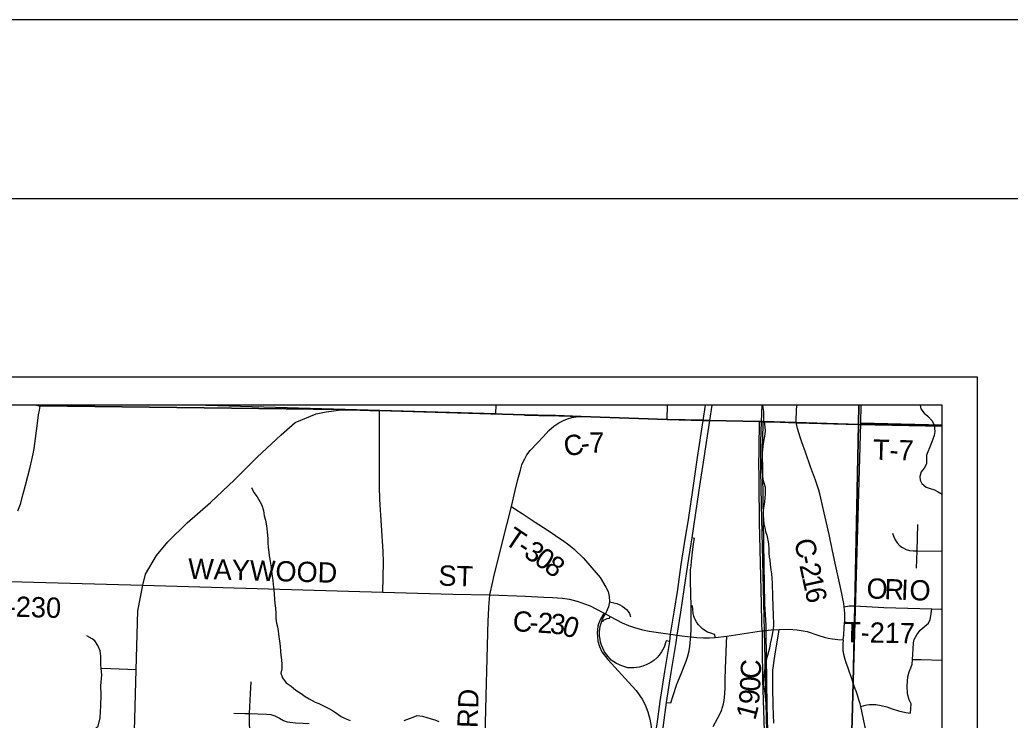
# Model space of a CAD drawing. Extents: x 0 to 34, y 0 to 22.
# Drawn here: x 7.053 to 9.827, y 20.038 to 22 of the extents above; entities that cross this region are included whole.
import ezdxf

# ---------------------------------------------------------------- set-up
doc = ezdxf.new("R2010")
doc.units = 0
for name, color, linetype in [('GM_X_Corporation', 7, 'Continuous'), ('GM_X_County_Road', 7, 'Continuous'), ('GM_X_County_Road_Text', 7, 'Continuous'), ('GM_X_Interchange_Ramps', 7, 'Continuous'), ('GM_X_Interstate_Route', 7, 'Continuous'), ('GM_X_Minor_River', 7, 'Continuous'), ('GM_X_Rail_Line', 7, 'Continuous'), ('GM_X_State_Route', 7, 'Continuous'), ('GM_X_Township_Road', 7, 'Continuous'), ('GM_X_Township_Road_Text', 7, 'Continuous'), ('SH_Border', 7, 'Continuous'), ('SH_Cut_Line', 7, 'Continuous'), ('SH_Data', 7, 'Continuous')]:
    doc.layers.add(name, color=color, linetype=linetype)

msp = doc.modelspace()

# ---------------------------------------------------------------- linework, layer by layer
at = {"layer": 'GM_X_Corporation'}
for points in [[(7.1023, 20.9204), (2.837, 20.9204), (2.837, 14.1204), (9.637, 14.1204), (9.637, 20.9204), (9.4036, 20.9204), (9.4022, 20.8667), (9.2273, 20.8723), (9.1354, 20.8749), (9.124, 20.8753), (8.9858, 20.878), (8.9676, 20.8785), (8.8663, 20.881), (8.6259, 20.8892), (8.5535, 20.8914), (8.5421, 20.8915), (8.4667, 20.8934), (8.0602, 20.9055), (7.9522, 20.9084), (7.1104, 20.9188)], [(9.4036, 20.9204), (7.1023, 20.9204), (7.1104, 20.9188), (7.9522, 20.9084), (8.0602, 20.9055), (8.4667, 20.8934), (8.5421, 20.8915), (8.5535, 20.8914), (8.6259, 20.8892), (8.8663, 20.881), (8.9676, 20.8785), (8.9858, 20.878), (9.124, 20.8753), (9.1354, 20.8749), (9.2273, 20.8723), (9.4022, 20.8667)], [(9.4038, 20.9204), (7.1023, 20.9204), (7.1104, 20.9188), (7.9522, 20.9084), (8.0602, 20.9055), (8.4667, 20.8934), (8.5422, 20.8918), (8.5472, 20.8916), (8.563, 20.8911), (8.6259, 20.8892), (8.8663, 20.881), (8.9858, 20.878), (9.124, 20.8753), (9.1354, 20.8749), (9.2299, 20.8713), (9.4022, 20.8667)], [(9.4036, 20.9204), (7.1023, 20.9204), (7.1104, 20.9188), (7.9522, 20.9084), (8.0602, 20.9055), (8.4667, 20.8934), (8.5421, 20.8915), (8.5535, 20.8914), (8.6259, 20.8892), (8.8663, 20.881), (8.9676, 20.8785), (8.9858, 20.878), (9.124, 20.8753), (9.1354, 20.8749), (9.2273, 20.8723), (9.4022, 20.8667)], [(8.3873, 20.9204), (7.5744, 20.9204), (8.3863, 20.8974)], [(9.637, 20.8621), (9.637, 20.9204), (9.4036, 20.9204), (9.4022, 20.8667)], [(9.637, 20.8648), (9.637, 20.9204), (9.4094, 20.9204), (9.4079, 20.8705)], [(9.637, 19.791), (9.637, 20.8648), (9.4079, 20.8705), (9.3789, 19.8558), (9.3773, 19.7981)]]:
    msp.add_lwpolyline(points, close=True, dxfattribs=at)
for points in [[(9.3802, 19.8717), (9.3877, 20.1427), (9.3918, 20.3593), (9.4022, 20.8667), (9.2273, 20.8723), (9.1354, 20.8749), (9.124, 20.8753), (8.9858, 20.878), (8.9676, 20.8785), (8.8663, 20.881), (8.6259, 20.8892), (8.5535, 20.8914), (8.5421, 20.8915), (8.4667, 20.8934), (8.0602, 20.9055), (7.9522, 20.9084), (7.1104, 20.9188), (7.1023, 20.9204), (3.3169, 20.9204)], [(9.1487, 20.0085), (9.1468, 20.0776), (9.145, 20.218), (9.1441, 20.2844), (9.144, 20.2867), (9.144, 20.2897), (9.144, 20.2906), (9.1437, 20.3035), (9.1399, 20.3642), (9.1383, 20.4738), (9.1364, 20.5986), (9.1357, 20.6613), (9.1334, 20.7956), (9.1352, 20.8657), (9.1354, 20.8749), (9.124, 20.8753), (9.1238, 20.8716), (9.1239, 20.8698), (9.1226, 20.7411), (9.1229, 20.7362), (9.1234, 20.6964), (9.1243, 20.5991), (9.1244, 20.5932), (9.1298, 20.3645), (9.131, 20.3111), (9.1312, 20.3022), (9.1326, 20.2879), (9.1327, 20.2847), (9.133, 20.2451), (9.1337, 20.1498), (9.1348, 20.1234), (9.138, 20.0088)], [(9.637, 14.7553), (9.637, 20.8621), (9.4022, 20.8667), (9.3918, 20.3593), (9.3877, 20.1427), (9.3802, 19.8717)]]:
    msp.add_lwpolyline(points, dxfattribs=at)
at = {"layer": 'GM_X_County_Road'}
for p, q in [((7.0998, 20.9204), (7.1106, 20.9182)), ((8.8665, 20.8805), (8.8676, 20.9204)), ((7.9524, 20.9078), (8.0064, 20.9064)), ((8.0064, 20.9064), (8.0604, 20.905)), ((8.4669, 20.8929), (8.5469, 20.8907)), ((8.6261, 20.8886), (8.8665, 20.8805)), ((9.1376, 20.8743), (9.2275, 20.8718)), ((9.2275, 20.8718), (9.4024, 20.8662)), ((6.9433, 20.4291), (7.3976, 20.4163))]:
    msp.add_line(p, q, dxfattribs=at)
for points in [[(9.2275, 20.8718), (9.2293, 20.9101), (9.2306, 20.9204)], [(8.4633, 20.7616), (8.4676, 20.7708), (8.4738, 20.782), (8.4828, 20.7933), (8.5036, 20.8155), (8.5189, 20.832), (8.5354, 20.8502), (8.549, 20.8622), (8.5629, 20.8716)], [(8.5629, 20.8716), (8.5761, 20.8781), (8.5877, 20.8826), (8.5993, 20.8858), (8.6118, 20.8877), (8.6261, 20.8886)], [(8.8665, 20.8805), (8.9678, 20.878), (8.9769, 20.8777)], [(8.9769, 20.8777), (8.986, 20.8775), (9.1242, 20.8748), (9.1273, 20.8747)], [(9.1273, 20.8747), (9.1356, 20.8744), (9.1376, 20.8743)], [(9.3625, 20.3556), (9.3611, 20.3652), (9.3586, 20.3784), (9.3554, 20.3931), (9.3473, 20.4311), (9.3383, 20.4736), (9.3289, 20.5176), (9.3202, 20.5583), (9.3068, 20.6194), (9.2972, 20.6605), (9.2941, 20.6722), (9.2912, 20.6823), (9.2818, 20.7105), (9.2685, 20.7477), (9.2537, 20.7894), (9.2437, 20.8168), (9.239, 20.8307), (9.2313, 20.8557), (9.2275, 20.8718)], [(8.3812, 20.4403), (8.4041, 20.5339), (8.4301, 20.6367), (8.4409, 20.6821), (8.4486, 20.7123), (8.4554, 20.7387), (8.4595, 20.7534), (8.4633, 20.7616)], [(8.3659, 20.3308), (8.3666, 20.3556), (8.3695, 20.3894), (8.3778, 20.4265), (8.3812, 20.4403)], [(7.3976, 20.4163), (8.07, 20.3969), (8.2661, 20.3914), (8.3695, 20.3894)], [(8.3695, 20.3894), (8.4699, 20.3855), (8.5215, 20.3832), (8.5453, 20.3824), (8.5737, 20.3802), (8.5926, 20.377), (8.6134, 20.3717), (8.6144, 20.3714)], [(8.6144, 20.3714), (8.6354, 20.3645), (8.6511, 20.3584), (8.6669, 20.3506), (8.6899, 20.3386)], [(8.6899, 20.3386), (8.6938, 20.3364), (8.7071, 20.3289), (8.7242, 20.3194), (8.7403, 20.3114), (8.7585, 20.3035), (8.7748, 20.2979), (8.797, 20.2919), (8.8161, 20.288), (8.862, 20.2813)], [(9.3627, 20.2985), (9.3638, 20.3185), (9.364, 20.3383), (9.3637, 20.3466), (9.3625, 20.3556)], [(8.3538, 19.8762), (8.3599, 20.1063), (8.3625, 20.2113), (8.3655, 20.3184), (8.3659, 20.3308)], [(8.862, 20.2813), (8.8763, 20.2792), (8.8946, 20.2767), (8.9077, 20.2751), (8.9234, 20.2729), (8.9326, 20.2719), (8.9494, 20.2702), (8.9684, 20.2691), (8.9848, 20.2688), (9.0008, 20.2697), (9.0334, 20.2737), (9.1311, 20.2884)], [(9.1311, 20.2884), (9.1359, 20.2891), (9.141, 20.2896)], [(9.141, 20.2896), (9.1582, 20.2913), (9.1805, 20.2928)], [(9.1651, 20.03), (9.1638, 20.0783), (9.1624, 20.1314), (9.1621, 20.1505), (9.1623, 20.1665), (9.1629, 20.1787), (9.1641, 20.1914), (9.1662, 20.2056), (9.17, 20.2298), (9.1784, 20.2789), (9.1805, 20.2928)], [(9.1805, 20.2928), (9.2062, 20.2935), (9.2309, 20.2917), (9.2583, 20.2864), (9.2915, 20.2754), (9.3061, 20.2706), (9.3179, 20.268), (9.3301, 20.266), (9.3449, 20.2646), (9.36, 20.2633)], [(9.36, 20.2633), (9.3616, 20.2765), (9.3627, 20.2985)], [(9.3948, 20.1222), (9.3942, 20.1239), (9.3879, 20.1422), (9.3847, 20.1519), (9.3725, 20.1869), (9.3681, 20.1993), (9.365, 20.2088), (9.361, 20.2222), (9.3601, 20.2288), (9.3599, 20.2315), (9.3599, 20.2353), (9.3597, 20.2415), (9.3599, 20.2553), (9.3601, 20.2608), (9.36, 20.2633)], [(9.4223, 20.0149), (9.4203, 20.0231), (9.409, 20.0769), (9.4068, 20.0838), (9.4033, 20.0959), (9.3994, 20.1083), (9.3948, 20.1222)]]:
    msp.add_lwpolyline(points, dxfattribs=at)
at = {"layer": 'GM_X_Interchange_Ramps'}
msp.add_line((8.9334, 20.358), (8.9319, 20.4275), dxfattribs=at)
for points in [[(8.9319, 20.4275), (8.9317, 20.434), (8.9317, 20.452), (8.9319, 20.4591), (8.9334, 20.4712), (8.9346, 20.4835), (8.9379, 20.5094), (8.9407, 20.5323), (8.9427, 20.5471), (8.937, 20.5487)], [(8.6899, 20.3386), (8.6874, 20.3341), (8.6787, 20.3193), (8.6745, 20.3085), (8.6725, 20.3013), (8.6712, 20.2917), (8.6704, 20.283), (8.6712, 20.273), (8.6726, 20.2598), (8.6767, 20.2451), (8.6831, 20.2301), (8.7001, 20.2081), (8.7688, 20.1341), (8.7796, 20.1219), (8.7885, 20.1099), (8.7962, 20.0973), (8.805, 20.0811), (8.8125, 20.0622), (8.818, 20.0414), (8.8214, 20.0209), (8.8233, 19.9995), (8.8239, 19.9901), (8.832, 19.9897)], [(8.8736, 20.2591), (8.8635, 20.2606), (8.8579, 20.2431), (8.8503, 20.2299), (8.8444, 20.2209), (8.8375, 20.2132), (8.8296, 20.2059), (8.8208, 20.2002), (8.8095, 20.1945), (8.7981, 20.1898), (8.7877, 20.187), (8.7733, 20.1849), (8.7562, 20.1854), (8.7395, 20.1902), (8.7249, 20.1971), (8.7101, 20.2069), (8.6974, 20.2216), (8.6909, 20.2299), (8.686, 20.2398), (8.6826, 20.2482), (8.6802, 20.2569), (8.6785, 20.2653), (8.6773, 20.2748), (8.6769, 20.2846), (8.6781, 20.2951), (8.6797, 20.3045), (8.6826, 20.3132), (8.6842, 20.3178), (8.6858, 20.3224), (8.6913, 20.332), (8.6938, 20.3364)], [(8.9326, 20.2719), (8.9329, 20.2762), (8.9342, 20.2927), (8.9342, 20.3044), (8.9342, 20.3149), (8.934, 20.33), (8.934, 20.3372), (8.9334, 20.3489), (8.9334, 20.358)], [(9.0008, 20.2697), (9.0002, 20.2788), (8.9961, 20.2797), (8.9889, 20.2817), (8.9798, 20.2851), (8.9722, 20.2895), (8.9657, 20.2942), (8.96, 20.3001), (8.9535, 20.3068), (8.9487, 20.3138), (8.945, 20.32), (8.9431, 20.3242), (8.9414, 20.3297), (8.9396, 20.3374), (8.9386, 20.3481), (8.9374, 20.3583), (8.9334, 20.358)], [(8.6842, 20.3178), (8.6875, 20.3159), (8.6905, 20.3191), (8.6944, 20.3216), (8.6989, 20.323), (8.7047, 20.3243), (8.7071, 20.3289)], [(8.9121, 20.1847), (8.9194, 20.2037), (8.9239, 20.2149), (8.9286, 20.2329), (8.9303, 20.2444), (8.9319, 20.2651), (8.9326, 20.2719)], [(8.8651, 20.0879), (8.877, 20.0871), (8.8831, 20.1076), (8.8939, 20.1391), (8.9057, 20.1679), (8.9121, 20.1847)]]:
    msp.add_lwpolyline(points, dxfattribs=at)
at = {"layer": 'GM_X_Interstate_Route'}
for p, q in [((8.9678, 20.878), (8.9742, 20.9204)), ((8.986, 20.8775), (8.9925, 20.9204))]:
    msp.add_line(p, q, dxfattribs=at)
for points in [[(8.8273, 19.9603), (8.832, 19.9897), (8.8381, 20.0277), (8.8472, 20.0907), (8.8602, 20.1746), (8.8736, 20.2591), (8.8763, 20.2792), (8.8862, 20.3413), (8.8962, 20.4047), (8.9061, 20.4741), (8.9155, 20.533), (8.9181, 20.5506), (8.926, 20.5995), (8.9382, 20.6828), (8.9516, 20.774), (8.9678, 20.878)], [(8.8465, 19.9599), (8.8511, 19.9887), (8.8561, 20.0249), (8.8651, 20.0879), (8.8781, 20.1718), (8.8916, 20.2563), (8.8946, 20.2767), (8.9044, 20.3409), (8.9144, 20.4042), (8.9243, 20.4736), (8.9337, 20.5325), (8.937, 20.5487), (8.9564, 20.6824), (8.9699, 20.7735), (8.986, 20.8775)]]:
    msp.add_lwpolyline(points, dxfattribs=at)
at = {"layer": 'GM_X_Minor_River'}
for points in [[(9.1381, 20.8737), (9.1369, 20.8771), (9.1375, 20.8908), (9.137, 20.9033), (9.1353, 20.9139), (9.1345, 20.9204)], [(9.5751, 20.9204), (9.577, 20.9109), (9.5867, 20.8981), (9.597, 20.8899), (9.6089, 20.8768), (9.6147, 20.8643), (9.6165, 20.8472), (9.6147, 20.8362), (9.611, 20.8255), (9.6055, 20.811), (9.6015, 20.8015), (9.5963, 20.79), (9.5926, 20.7805), (9.5929, 20.7566), (9.5862, 20.7447), (9.5776, 20.734), (9.574, 20.7211), (9.5749, 20.7108), (9.5803, 20.701), (9.5918, 20.6909), (9.6036, 20.6876), (9.6158, 20.6832), (9.6257, 20.678), (9.637, 20.6719)], [(9.1381, 20.8737), (9.1401, 20.8603), (9.141, 20.8478), (9.1389, 20.8337), (9.1364, 20.8189), (9.1343, 20.8059), (9.1333, 20.796), (9.1326, 20.7865), (9.1324, 20.7763), (9.1321, 20.7653), (9.1319, 20.7554), (9.132, 20.7448), (9.1329, 20.7338), (9.1334, 20.7232), (9.1347, 20.7122), (9.1382, 20.7008), (9.141, 20.6906), (9.1412, 20.6716), (9.1406, 20.6617), (9.1388, 20.6492), (9.1374, 20.6389), (9.1357, 20.626), (9.1351, 20.6131), (9.136, 20.6017), (9.1377, 20.5884), (9.1401, 20.5774), (9.1421, 20.5668), (9.1453, 20.5566), (9.1485, 20.5422), (9.1505, 20.5324), (9.1514, 20.5176), (9.1516, 20.5058), (9.1524, 20.4963), (9.1537, 20.4865), (9.155, 20.4743), (9.1571, 20.4592), (9.1587, 20.4486), (9.16, 20.4357), (9.1605, 20.4243), (9.161, 20.414), (9.1613, 20.3928), (9.1618, 20.378), (9.1624, 20.3639), (9.1625, 20.3514), (9.1631, 20.3389), (9.1632, 20.3271), (9.1641, 20.3138), (9.1643, 20.3017), (9.1625, 20.2895), (9.1604, 20.2774), (9.1575, 20.264), (9.155, 20.2526), (9.1529, 20.2404), (9.15, 20.2298), (9.1478, 20.2199), (9.1449, 20.21), (9.142, 20.1963), (9.1399, 20.1845), (9.1385, 20.1731), (9.1375, 20.1636), (9.1362, 20.1484), (9.1363, 20.1377), (9.1388, 20.1203), (9.1412, 20.1059), (9.1421, 20.0957), (9.1434, 20.0839), (9.1439, 20.0725), (9.1448, 20.0581), (9.145, 20.046), (9.1455, 20.035)], [(7.7024, 20.6898), (7.709, 20.6762), (7.7183, 20.6638), (7.726, 20.6509), (7.7311, 20.6404), (7.7354, 20.6256), (7.7379, 20.6112), (7.7411, 20.5991), (7.7443, 20.5824), (7.7469, 20.5566), (7.7478, 20.5464), (7.7483, 20.535), (7.7492, 20.5217), (7.7505, 20.5089), (7.7521, 20.499), (7.7534, 20.4895), (7.7554, 20.477), (7.7571, 20.466), (7.7583, 20.4554), (7.7604, 20.4421), (7.7621, 20.4296), (7.763, 20.4183), (7.7643, 20.4038), (7.7656, 20.3913), (7.7665, 20.3773), (7.7674, 20.3652), (7.7691, 20.3526), (7.77, 20.3386), (7.7702, 20.3234), (7.7722, 20.3105), (7.7746, 20.3003), (7.7767, 20.2886), (7.7775, 20.2791), (7.7808, 20.2594), (7.7821, 20.2461), (7.7834, 20.2309), (7.7843, 20.2207), (7.786, 20.207), (7.7869, 20.1953), (7.7871, 20.1824), (7.7842, 20.1698), (7.7893, 20.1566), (7.7997, 20.1434), (7.813, 20.1341), (7.8268, 20.1225), (7.8414, 20.1132), (7.8525, 20.1046), (7.8635, 20.0982), (7.8807, 20.0889), (7.891, 20.0849), (7.9055, 20.0775), (7.9173, 20.0719), (7.9291, 20.0652), (7.9406, 20.0577), (7.9536, 20.0492), (7.9643, 20.0436), (7.9784, 20.0377)], [(8.1297, 20.0372), (8.1444, 20.0434), (8.155, 20.0469), (8.1659, 20.0513), (8.1811, 20.0495), (8.1933, 20.0463), (8.2055, 20.0422), (8.2153, 20.0393), (8.2268, 20.0349)]]:
    msp.add_lwpolyline(points, dxfattribs=at)
at = {"layer": 'GM_X_Rail_Line'}
msp.add_line((9.1304, 20.8739), (9.1324, 20.9204), dxfattribs=at)
msp.add_lwpolyline([(9.1525, 19.7238), (9.1393, 20.2883), (9.1311, 20.6426), (9.1288, 20.7377), (9.1285, 20.7773), (9.1291, 20.8186), (9.1304, 20.8739)], dxfattribs=at)
at = {"layer": 'GM_X_State_Route'}
msp.add_line((7.1106, 20.9182), (7.1112, 20.9204), dxfattribs=at)
msp.add_lwpolyline([(7.0481, 20.6246), (7.0547, 20.6439), (7.0627, 20.6722), (7.069, 20.6966), (7.082, 20.7469), (7.0873, 20.768), (7.0908, 20.784), (7.0936, 20.7993), (7.0957, 20.8134), (7.1019, 20.8631), (7.106, 20.8939), (7.1079, 20.9065), (7.1106, 20.9182)], dxfattribs=at)
at = {"layer": 'GM_X_Township_Road'}
for p, q in [((7.0998, 20.9204), (7.1106, 20.9182)), ((7.9524, 20.9078), (8.0064, 20.9064)), ((8.0064, 20.9064), (8.0604, 20.905)), ((9.2275, 20.8718), (9.4024, 20.8662)), ((9.4024, 20.8662), (9.637, 20.8616))]:
    msp.add_line(p, q, dxfattribs=at)
for points in [[(7.3976, 20.4163), (7.4054, 20.4471), (7.4357, 20.4993), (7.4674, 20.5378), (7.5219, 20.5908), (7.5869, 20.6483), (7.6549, 20.7118), (7.7185, 20.7753), (7.785, 20.8373), (7.8243, 20.8721), (7.8833, 20.8963), (7.9118, 20.9025), (7.9463, 20.907), (7.9524, 20.9078)], [(8.07, 20.3969), (8.0715, 20.4814), (8.0709, 20.5108), (8.0621, 20.6564), (8.0607, 20.6929), (8.0607, 20.7942), (8.0604, 20.905)], [(8.4301, 20.6367), (8.4423, 20.6287), (8.4608, 20.6169), (8.4971, 20.5934), (8.5308, 20.5713), (8.554, 20.5561), (8.5769, 20.5401), (8.5872, 20.5325), (8.5955, 20.526), (8.6047, 20.5185), (8.6147, 20.5094), (8.6236, 20.5008), (8.6312, 20.4927), (8.6378, 20.4853), (8.6443, 20.4779), (8.6785, 20.438)], [(9.5651, 20.4645), (9.567, 20.5132), (9.5688, 20.5865)], [(9.4977, 20.5619), (9.5014, 20.5519), (9.5048, 20.5433), (9.5107, 20.5347), (9.518, 20.5271), (9.5254, 20.522), (9.5359, 20.5168), (9.5457, 20.5139), (9.5569, 20.5132), (9.567, 20.5132), (9.637, 20.5114)], [(8.6785, 20.438), (8.6946, 20.411), (8.7009, 20.3993), (8.704, 20.3851), (8.7053, 20.37), (8.7021, 20.3561), (8.6987, 20.3475), (8.6938, 20.3364)], [(7.3406, 18.8914), (7.3442, 19.0642), (7.3475, 19.2211), (7.3532, 19.284), (7.357, 19.3966), (7.3638, 19.7171), (7.3719, 19.9057), (7.3787, 20.1798), (7.3838, 20.3445), (7.3976, 20.4163)], [(8.7053, 20.37), (8.7174, 20.3675), (8.7256, 20.3649), (8.734, 20.3613), (8.7406, 20.3576), (8.7474, 20.3531), (8.7528, 20.348), (8.7574, 20.3432), (8.7615, 20.3368), (8.7642, 20.328)], [(9.3625, 20.3556), (9.367, 20.357), (9.3724, 20.3581)], [(9.3724, 20.3581), (9.3768, 20.3587), (9.3802, 20.3588), (9.392, 20.3587), (9.4732, 20.3545), (9.6084, 20.35), (9.633, 20.3498), (9.637, 20.3495)], [(9.5485, 20.0577), (9.5496, 20.0838), (9.5447, 20.0955), (9.5402, 20.1125), (9.539, 20.1345), (9.5409, 20.1598), (9.544, 20.1734), (9.5489, 20.1848), (9.5527, 20.195), (9.5542, 20.2086), (9.5557, 20.238), (9.5564, 20.255), (9.5587, 20.2645), (9.5655, 20.2777), (9.575, 20.2902), (9.5984, 20.3103), (9.6033, 20.3205), (9.6056, 20.3303), (9.6084, 20.35)], [(7.3787, 20.1798), (7.3077, 20.1826), (7.281, 20.1834), (7.28, 20.1944), (7.2803, 20.2175), (7.2786, 20.2331), (7.2722, 20.248), (7.263, 20.2604), (7.2559, 20.2661), (7.241, 20.2743)], [(8.9957, 20.021), (9.008, 20.0435), (9.0151, 20.0574), (9.0187, 20.066), (9.0217, 20.0749), (9.0241, 20.084), (9.0258, 20.0932), (9.027, 20.1025), (9.0279, 20.1132), (9.0288, 20.1292), (9.029, 20.1367), (9.0294, 20.1522), (9.0302, 20.1833), (9.0317, 20.2285), (9.033, 20.2542), (9.0334, 20.2737)], [(9.5542, 20.2086), (9.5776, 20.2086), (9.637, 20.2069)], [(7.1298, 19.994), (7.1428, 19.9938), (7.162, 19.9938), (7.1833, 19.9959), (7.2004, 19.9987), (7.2252, 20.0009), (7.248, 20.0073), (7.2636, 20.0143), (7.2728, 20.0221), (7.2785, 20.0449), (7.28, 20.079), (7.2807, 20.1095), (7.28, 20.1351), (7.2828, 20.1656), (7.281, 20.1834)], [(7.6969, 20.0521), (7.697, 20.0567), (7.6994, 20.1136), (7.7013, 20.1459)], [(7.653, 20.0579), (7.6832, 20.0573), (7.697, 20.0567), (7.7439, 20.055), (7.7561, 20.0541), (7.768, 20.0506), (7.7807, 20.0437), (7.792, 20.0376), (7.8024, 20.0341), (7.825, 20.0312), (7.8473, 20.0304), (7.8641, 20.0295)], [(9.409, 20.0769), (9.4184, 20.0799), (9.426, 20.0814), (9.4331, 20.0823), (9.44, 20.0825), (9.4515, 20.0821), (9.4657, 20.08), (9.4823, 20.0755), (9.4971, 20.0702), (9.5141, 20.0649), (9.5349, 20.0603), (9.5485, 20.0577)], [(7.7083, 19.8943), (7.7115, 19.9377), (7.7121, 19.9563), (7.7109, 19.9719), (7.7078, 19.9869), (7.7008, 20.0057), (7.6979, 20.0162), (7.6965, 20.0266), (7.6965, 20.0428), (7.6969, 20.0521)]]:
    msp.add_lwpolyline(points, dxfattribs=at)
at = {"layer": 'SH_Border'}
msp.add_lwpolyline([(1.5, 21.5), (33.5, 21.5), (33.5, 0.5), (1.5, 0.5)], close=True, dxfattribs=at)
at = {"layer": 'SH_Cut_Line'}
msp.add_lwpolyline([(0, 0), (34, 0), (34, 22), (0, 22)], close=True, dxfattribs=at)
at = {"layer": 'SH_Data'}
for p, q in [((2.7349, 21.0001), (9.7349, 21.0001)), ((9.7349, 21.0001), (9.7349, 14.0001))]:
    msp.add_line(p, q, dxfattribs=at)

# ---------------------------------------------------------------- texts
at = {"layer": 'GM_X_County_Road_Text'}
for s, height, rotation, p in [('C', 0.0568, 10.3164, (8.5823, 20.7763)), ('7', 0.0568, 1.3271, (8.6491, 20.7873)), ('-', 0.0568, 7.2005, (8.6274, 20.7845)), ('C', 0.0568, 282.1626, (9.2219, 20.541)), ('WAYWOOD', 0.05682, 358.3741, (7.5239, 20.4348)), ('2', 0.0568, 282.1823, (9.2366, 20.4725)), ('-', 0.0568, 282.1596, (9.2317, 20.4954)), ('ST', 0.05682, 358.2478, (8.2251, 20.4156)), ('1', 0.0568, 282.2726, (9.244, 20.4382)), ('6', 0.0568, 282.561, (9.2515, 20.4037)), ('C-230', 0.05682, 358.3486, (6.9612, 20.3305)), ('C', 0.0568, 356.5281, (8.4327, 20.2881)), ('2', 0.0568, 356.3964, (8.5026, 20.2838)), ('3', 0.0568, 353.8529, (8.5368, 20.2817)), ('-', 0.0568, 356.5006, (8.4793, 20.2852)), ('0', 0.0568, 343.1138, (8.5689, 20.2785)), ('RD', 0.05682, 88.0243, (8.3353, 20.0157))]:
    msp.add_text(s, height=height, rotation=rotation, dxfattribs=at).set_placement(p)
at = {"layer": 'GM_X_Township_Road_Text'}
for s, height, rotation, p in [('T-7', 0.05682, 358.5669, (9.4424, 20.7682)), ('T', 0.0568, 325.9735, (8.407, 20.5353)), ('-', 0.0568, 325.9635, (8.4422, 20.5116)), ('3', 0.0568, 325.9029, (8.4615, 20.4985)), ('0', 0.0568, 325.6965, (8.4905, 20.4789)), ('8', 0.0568, 323.1821, (8.5188, 20.4596)), ('O', 0.0568, 357.668, (9.4242, 20.3798)), ('R', 0.0568, 357.6715, (9.4742, 20.3777)), ('I', 0.0568, 357.6713, (9.5208, 20.3758)), ('O', 0.0568, 357.8814, (9.5444, 20.3749)), ('T-217', 0.05682, 358.8825, (9.3617, 20.2572)), ('C', 0.0568, 87.4886, (9.1282, 20.153)), ('0', 0.0568, 87.2482, (9.1265, 20.1178)), ('9', 0.0568, 85.51, (9.1236, 20.081)), ('1', 0.0568, 75.3689, (9.113, 20.0363))]:
    msp.add_text(s, height=height, rotation=rotation, dxfattribs=at).set_placement(p)

doc.saveas('drawing.dxf')
